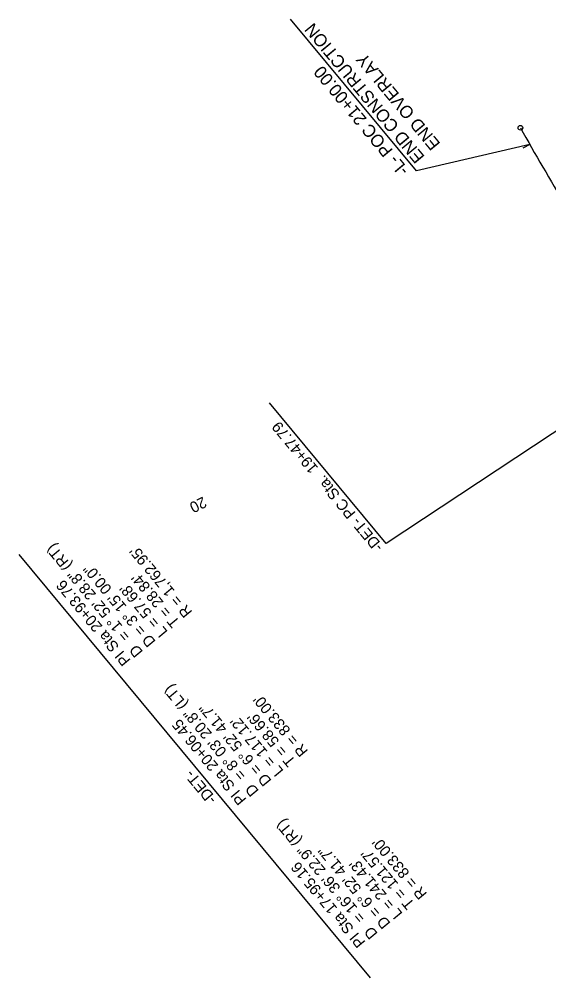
# Model space of a CAD drawing. Extents: x 2597390 to 2598563, y 852595 to 853909.
# Drawn here: x 2597390 to 2597728, y 853172 to 853783 of the extents above; entities that cross this region are included whole.
import ezdxf

# ---------------------------------------------------------------- set-up
doc = ezdxf.new("R2010")
doc.units = 0
for name, color, linetype in [('Prop DSN Text', 7, 'Continuous'), ('Prop Horizontal Alignment', 7, 'Continuous'), ('Prop Horizontal Alignment Curve and Spiral Data', 7, 'Continuous'), ('Prop Horizontal Alignment Station Label', 7, 'Continuous'), ('Prop Horizontal Alignment Tick Label', 7, 'Continuous'), ('Prop Horizontal Alignment Tick Small', 7, 'Continuous'), ('Prop Leader Line Medium', 7, 'Continuous')]:
    doc.layers.add(name, color=color, linetype=linetype)

msp = doc.modelspace()

# ---------------------------------------------------------------- linework, layer by layer
at = {"layer": 'Prop Horizontal Alignment'}
msp.add_arc((2599247.12, 854575.63), 1762.95, 209.28143, 211.1561, dxfattribs=at)
at = {"layer": 'Prop Horizontal Alignment Station Label'}
for p, q in [((2597790.57, 853558.55), (2597623.9, 853448.45)), ((2597623.9, 853448.45), (2597549.46, 853538.09)), ((2597613.84, 853171.66), (2597389.78, 853441.48))]:
    msp.add_line(p, q, dxfattribs=at)
msp.add_circle((2597709.43, 853713.37), 1.5, dxfattribs=at)
at = {"layer": 'Prop Horizontal Alignment Tick Small'}
msp.add_line((2597715.4, 853702.82), (2597711.05, 853700.34), dxfattribs=at)
at = {"layer": 'Prop Leader Line Medium'}
for p, q in [((2597643.1, 853685.9), (2597562.8, 853782.6)), ((2597715.4, 853702.82), (2597643.1, 853685.9))]:
    msp.add_line(p, q, dxfattribs=at)

# ---------------------------------------------------------------- texts
at = {"layer": 'Prop DSN Text'}
for s, p in [('END CONSTRUCTION', (2597648.79, 853694.94)), ('END OVERLAY', (2597658.79, 853703.25)), ('-L- POC 21+00.00', (2597638.79, 853686.64))]:
    msp.add_text(s, height=8, rotation=129.70669, dxfattribs=at).set_placement(p)
at = {"layer": 'Prop Horizontal Alignment Curve and Spiral Data'}
for s, p in [('= 1%%d 52\' 28.8" (RT)', (2597461.18, 853389.64)), ("R = 1,762.95'", (2597500.52, 853404.84)), ('D = 3%%d 15\' 00.0"', (2597477.21, 853386.05)), ('PI Sta 20+93.76', (2597461.23, 853374.04)), ("T = 28.84'", (2597492.67, 853398.52)), ("L = 57.68'", (2597484.87, 853392.22)), ('D', (2597469.06, 853379.48)), ('= 8%%d 03\' 20.8" (LT)', (2597535.07, 853301)), ("R = 833.00'", (2597574.39, 853316.18)), ('D = 6%%d 52\' 41.7"', (2597551.09, 853297.4)), ("L = 117.12'", (2597558.74, 853303.57)), ("T = 58.66'", (2597566.56, 853309.87)), ('PI Sta 20+06.45', (2597535.12, 853285.39)), ('-DET-', (2597516.13, 853285.74)), ('D', (2597542.95, 853290.83)), ('= 16%%d 36\' 22.9" (RT)', (2597610.98, 853210.08)), ("R = 833.00'", (2597650.26, 853225.25)), ('D = 6%%d 52\' 41.7"', (2597626.97, 853206.46)), ("L = 241.43'", (2597634.65, 853212.66)), ("T = 121.57'", (2597642.44, 853218.93)), ('PI Sta 17+95.16', (2597610.96, 853194.42)), ('D', (2597618.82, 853199.89))]:
    msp.add_text(s, height=7, rotation=129.70669, dxfattribs=at).set_placement(p)
at = {"layer": 'Prop Horizontal Alignment Station Label'}
msp.add_text('-DET- PC Sta.  19+47.79', height=7, rotation=129.70669, dxfattribs=at).set_placement((2597622.36, 853446.65))
at = {"layer": 'Prop Horizontal Alignment Tick Label'}
msp.add_text('20', height=7, rotation=206.69116, dxfattribs=at).set_placement((2597507.06, 853478.52))

doc.saveas('drawing.dxf')
